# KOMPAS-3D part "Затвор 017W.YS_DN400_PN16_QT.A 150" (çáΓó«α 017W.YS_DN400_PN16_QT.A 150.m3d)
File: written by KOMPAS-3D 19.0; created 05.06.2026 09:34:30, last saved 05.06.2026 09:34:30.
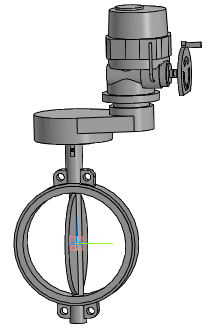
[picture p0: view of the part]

Document properties: Автор: Энергия; Полное имя файла: ..\..\..\3d для проектировщиков\x.x Тип 017W.Y(S) Затвор дисковый поворотный межфланцевый\Затвор 017W.YS_DN400_PN16_QT.A 1501.a3d

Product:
- Part/product: Затвор 017W.YS_DN400_PN16_QT.A 150
    Масса: 252.015

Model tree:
1. Операция без истории:1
